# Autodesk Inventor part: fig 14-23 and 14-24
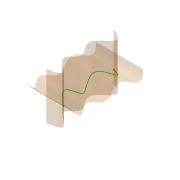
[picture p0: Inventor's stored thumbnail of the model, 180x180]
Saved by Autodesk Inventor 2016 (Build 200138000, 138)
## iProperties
Created: 2007-05
Part Number: fig 14-23 and 14-24
Document SubType Name: Modeling
Designer: Administrator
Density: 1 g/cm^3
Material: Generic
Appearance: Default
Author: Administrator
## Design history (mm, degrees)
node "Sketch1"
node "Sketch2"
sketch "Sketch3"
  geometry: 7 further points
  constraints: 7 other
extrude_surface "ExtrusionSrf1" sketch "Sketch3" dims "d0" = 50, "d1" = 0
sketch "Sketch4"
  geometry: 7 further points
  constraints: 7 other
extrude_surface "ExtrusionSrf2" sketch "Sketch4" dims "d2" = 50, "d3" = 0
sketch "3D Sketch1"
  node "3D Intersection1"
body "Srf1"
body "Srf2"
